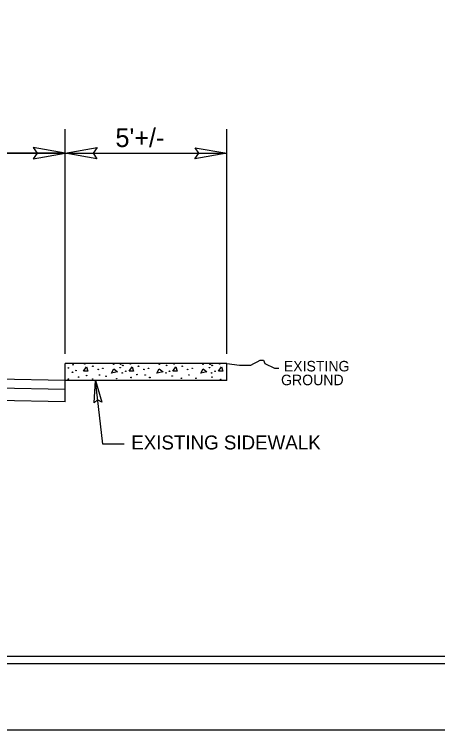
# Model space of a CAD drawing. Extents: x 1022283 to 1026986, y 174822 to 180471.
# Drawn here: x 1024272 to 1024632, y 177721 to 178329 of the extents above; entities that cross this region are included whole.
import ezdxf

# ---------------------------------------------------------------- set-up
doc = ezdxf.new("R2010")
doc.units = 0
for name, color, linetype in [('Default', 7, 'Continuous'), ('Prop Dimension', 7, 'Continuous'), ('Prop Terminator CELL', 7, 'Continuous'), ('Sheet Cutting Line CELL', 7, 'Continuous'), ('Sheet Plot Border Inside CELL', 7, 'Continuous'), ('Sheet Plot Border Outside CELL', 7, 'Continuous'), ('Sheet Typical CELL', 7, 'Continuous'), ('Typical Curb CELL', 7, 'Continuous'), ('Typical Slope Point Local CELL', 7, 'Continuous'), ('Typical Text General CELL', 7, 'Continuous')]:
    doc.layers.add(name, color=color, linetype=linetype)

# ---------------------------------------------------------------- blocks, each defined once
blk = doc.blocks.new('Terminator')
at = {"layer": 'Prop Terminator CELL'}
blk.add_lwpolyline([(-9, 1.55), (0, 0), (-9.05, -1.6), (-7.9, 0)], close=True, dxfattribs=at)

msp = doc.modelspace()

# ---------------------------------------------------------------- linework, layer by layer
at = {"layer": 'Default'}
for p, q in [((1024315.21, 178040.74), (1024315.21, 178231.56)), ((1024452.59, 178040.74), (1024452.59, 178231.56)), ((1023807.5, 178211), (1024315.21, 178211)), ((1024315.21, 178211), (1023807.5, 178211)), ((1024315.21, 178211), (1024452.59, 178211))]:
    msp.add_line(p, q, dxfattribs=at)
at = {"layer": 'Prop Dimension'}
for p, q in [((1024315.21, 178017.95), (1023807.5, 178028.1)), ((1024315.21, 178017.95), (1023807.5, 178028.1)), ((1024315.21, 178010.45), (1023807.5, 178020.6)), ((1024315.21, 178010.45), (1023807.5, 178020.6)), ((1024347.16, 177963.86), (1024340.91, 178017.95)), ((1024315.21, 177999.86), (1023807.5, 178010.02)), ((1024365.31, 177963.86), (1024347.16, 177963.86))]:
    msp.add_line(p, q, dxfattribs=at)
at = {"layer": 'Prop Terminator CELL'}
for points in [[(1024288.21, 178206.35), (1024315.21, 178211), (1024288.06, 178215.8), (1024291.51, 178211)], [(1024342.21, 178206.35), (1024315.21, 178211), (1024342.36, 178215.8), (1024338.91, 178211)], [(1024425.59, 178215.65), (1024452.59, 178211), (1024425.44, 178206.2), (1024428.89, 178211)]]:
    msp.add_lwpolyline(points, close=True, dxfattribs=at)
at = {"layer": 'Sheet Cutting Line CELL'}
msp.add_line((1022283.22, 177721.48), (1026493.22, 177721.48), dxfattribs=at)
at = {"layer": 'Sheet Plot Border Inside CELL'}
msp.add_lwpolyline([(1026481.97, 180415.35), (1022315.72, 180415.35), (1022315.72, 177777.6), (1026481.97, 177777.6)], close=True, dxfattribs=at)
at = {"layer": 'Sheet Plot Border Outside CELL'}
msp.add_lwpolyline([(1026493.22, 180471.48), (1022283.22, 180471.48), (1022283.22, 177721.48), (1026493.22, 177721.48)], close=True, dxfattribs=at)
at = {"layer": 'Sheet Typical CELL'}
msp.add_lwpolyline([(1026450.72, 180408.98), (1022700.72, 180408.98), (1022700.72, 177783.98), (1026450.72, 177783.98)], close=True, dxfattribs=at)
at = {"layer": 'Typical Curb CELL'}
for p, q in [((1024315.21, 178001.47), (1024315.21, 178032.47)), ((1024315.21, 178022.14), (1024315.21, 178032.47)), ((1024315.21, 178022.14), (1024315.21, 178032.47)), ((1024452.59, 178032.47), (1024315.21, 178032.47)), ((1024315.21, 177999.86), (1024315.21, 178032.47)), ((1024315.21, 178001.47), (1024315.21, 178032.47)), ((1024315.21, 178022.14), (1024315.21, 178032.47)), ((1024315.21, 178022.14), (1024315.21, 178032.47)), ((1024452.59, 178032.47), (1024315.21, 178032.47)), ((1024315.21, 177999.86), (1024315.21, 178032.47)), ((1024452.59, 178017.95), (1024452.59, 178032.47)), ((1024452.59, 178017.95), (1024452.59, 178032.47)), ((1024330.79, 178025.84), (1024333.47, 178029.56)), ((1024330.79, 178025.84), (1024333.47, 178029.56)), ((1024334.54, 178026.04), (1024330.79, 178025.84)), ((1024334.54, 178026.04), (1024330.79, 178025.84)), ((1024333.47, 178029.56), (1024334.54, 178026.04)), ((1024333.47, 178029.56), (1024334.54, 178026.04)), ((1024354.53, 178024.26), (1024356.47, 178027.81)), ((1024354.53, 178024.26), (1024356.47, 178027.81)), ((1024359.66, 178025.49), (1024354.53, 178024.26)), ((1024359.66, 178025.49), (1024354.53, 178024.26)), ((1024356.47, 178027.81), (1024359.66, 178025.49)), ((1024356.47, 178027.81), (1024359.66, 178025.49)), ((1024369.55, 178025.84), (1024372.19, 178029.56)), ((1024369.55, 178025.84), (1024372.19, 178029.56)), ((1024373.26, 178026.04), (1024369.55, 178025.84)), ((1024373.26, 178026.04), (1024369.55, 178025.84)), ((1024372.19, 178029.56), (1024373.26, 178026.04)), ((1024372.19, 178029.56), (1024373.26, 178026.04)), ((1024393.25, 178024.26), (1024395.19, 178027.81)), ((1024393.25, 178024.26), (1024395.19, 178027.81)), ((1024398.39, 178025.49), (1024393.25, 178024.26)), ((1024398.39, 178025.49), (1024393.25, 178024.26)), ((1024395.19, 178027.81), (1024398.39, 178025.49)), ((1024395.19, 178027.81), (1024398.39, 178025.49)), ((1024406.68, 178025.84), (1024409.36, 178029.56)), ((1024406.68, 178025.84), (1024409.36, 178029.56)), ((1024410.43, 178026.04), (1024406.68, 178025.84)), ((1024410.43, 178026.04), (1024406.68, 178025.84)), ((1024409.36, 178029.56), (1024410.43, 178026.04)), ((1024409.36, 178029.56), (1024410.43, 178026.04)), ((1024430.42, 178024.26), (1024432.36, 178027.81)), ((1024430.42, 178024.26), (1024432.36, 178027.81)), ((1024435.55, 178025.49), (1024430.42, 178024.26)), ((1024435.55, 178025.49), (1024430.42, 178024.26)), ((1024432.36, 178027.81), (1024435.55, 178025.49)), ((1024432.36, 178027.81), (1024435.55, 178025.49)), ((1024445.44, 178025.84), (1024448.08, 178029.56)), ((1024445.44, 178025.84), (1024448.08, 178029.56)), ((1024449.15, 178026.04), (1024445.44, 178025.84)), ((1024449.15, 178026.04), (1024445.44, 178025.84)), ((1024448.08, 178029.56), (1024449.15, 178026.04)), ((1024448.08, 178029.56), (1024449.15, 178026.04)), ((1024452.59, 178017.95), (1024315.21, 178017.95))]:
    msp.add_line(p, q, dxfattribs=at)
for centre in [(1024322.01, 178031.35), (1024322.01, 178031.35), (1024331.87, 178032.05), (1024331.87, 178032.05), (1024356.47, 178031.87), (1024356.47, 178031.87), (1024362.49, 178031.87), (1024362.49, 178031.87), (1024370.6, 178032.05), (1024370.6, 178032.05), (1024395.21, 178031.87), (1024395.21, 178031.87), (1024407.76, 178032.05), (1024407.76, 178032.05), (1024432.36, 178031.87), (1024432.36, 178031.87), (1024438.38, 178031.87), (1024438.38, 178031.87), (1024446.49, 178032.05), (1024446.49, 178032.05), (1024318.07, 178028.67), (1024318.07, 178028.67), (1024321.52, 178024.98), (1024321.52, 178024.98), (1024324.5, 178026.39), (1024324.5, 178026.39), (1024338.77, 178030.11), (1024338.77, 178030.11), (1024343.38, 178027.45), (1024343.38, 178027.45), (1024347.27, 178028.33), (1024347.27, 178028.33), (1024361.96, 178028.87), (1024361.96, 178028.87), (1024364.23, 178030.82), (1024364.23, 178030.82), (1024366.71, 178025.86), (1024366.71, 178025.86), (1024377.51, 178030.11), (1024377.51, 178030.11), (1024382.11, 178027.45), (1024382.11, 178027.45), (1024386.01, 178028.33), (1024386.01, 178028.33), (1024401.38, 178030.82), (1024401.38, 178030.82), (1024403.87, 178025.86), (1024403.87, 178025.86), (1024414.66, 178030.11), (1024414.66, 178030.11), (1024419.27, 178027.45), (1024419.27, 178027.45), (1024423.16, 178028.33), (1024423.16, 178028.33), (1024437.85, 178028.87), (1024437.85, 178028.87), (1024440.12, 178030.82), (1024440.12, 178030.82), (1024442.6, 178025.86), (1024442.6, 178025.86), (1024318.07, 178019.17), (1024318.07, 178019.17), (1024326.67, 178020.91), (1024326.67, 178020.91), (1024333.51, 178022.21), (1024333.51, 178022.21), (1024338.62, 178019.3), (1024338.62, 178019.3), (1024344.43, 178022.67), (1024344.43, 178022.67), (1024350.05, 178021.62), (1024350.05, 178021.62), (1024359.03, 178019.56), (1024359.03, 178019.56), (1024363.73, 178024.44), (1024363.73, 178024.44), (1024371.23, 178020.53), (1024371.23, 178020.53), (1024376.21, 178023.05), (1024376.21, 178023.05), (1024383.17, 178022.67), (1024383.17, 178022.67), (1024387.19, 178020.53), (1024387.19, 178020.53), (1024400.89, 178024.44), (1024400.89, 178024.44), (1024406.11, 178021.82), (1024406.11, 178021.82), (1024414, 178019.94), (1024414, 178019.94), (1024420.32, 178022.67), (1024420.32, 178022.67), (1024426.27, 178019.94), (1024426.27, 178019.94), (1024439.62, 178024.44), (1024439.62, 178024.44), (1024439.96, 178020.91), (1024439.96, 178020.91), (1024447.39, 178018.97), (1024447.39, 178018.97)]:
    msp.add_circle(centre, 0.249, dxfattribs=at)
at = {"layer": 'Typical Slope Point Local CELL'}
msp.add_lwpolyline([(1024452.59, 178032.47), (1024463.36, 178031.13), (1024466.05, 178031.13), (1024470.1, 178031.13), (1024472.79, 178031.13), (1024475.48, 178032.47), (1024478.18, 178033.83), (1024480.87, 178035.18), (1024483.56, 178035.18), (1024484.91, 178032.47), (1024487.61, 178031.13), (1024490.3, 178029.78), (1024492.99, 178028.44), (1024495.69, 178028.44), (1024496.75, 178028.44)], dxfattribs=at)
msp.add_lwpolyline([(1024452.59, 178032.47), (1024463.36, 178031.13), (1024466.05, 178031.13), (1024470.1, 178031.13), (1024472.79, 178031.13), (1024475.48, 178032.47), (1024478.18, 178033.83), (1024480.87, 178035.18), (1024483.56, 178035.18), (1024484.91, 178032.47), (1024487.61, 178031.13), (1024490.3, 178029.78), (1024492.99, 178028.44), (1024495.69, 178028.44), (1024496.75, 178028.44)], dxfattribs=at)

# ---------------------------------------------------------------- block references
at = {"layer": 'Prop Dimension', "xscale": 2.0767499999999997, "yscale": 2.076749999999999, "rotation": 96.5883266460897}
msp.add_blockref('Terminator', (1024340.91, 178017.95), dxfattribs=at)

# ---------------------------------------------------------------- texts
at = {"layer": 'Prop Dimension'}
msp.add_text("5'+/-", height=16, dxfattribs=at).set_placement((1024357.97, 178216.26))
at = {"layer": 'Typical Slope Point Local CELL'}
for s, p in [('EXISTING ', (1024500.91, 178025.72)), ('EXISTING ', (1024500.91, 178025.72)), ('GROUND', (1024498.58, 178014)), ('GROUND', (1024498.58, 178014))]:
    msp.add_text(s, height=8.938, dxfattribs=at).set_placement(p)
at = {"layer": 'Typical Text General CELL'}
msp.add_text('EXISTING SIDEWALK', height=11.8979, dxfattribs=at).set_placement((1024371.36, 177959.43))

doc.saveas('drawing.dxf')
